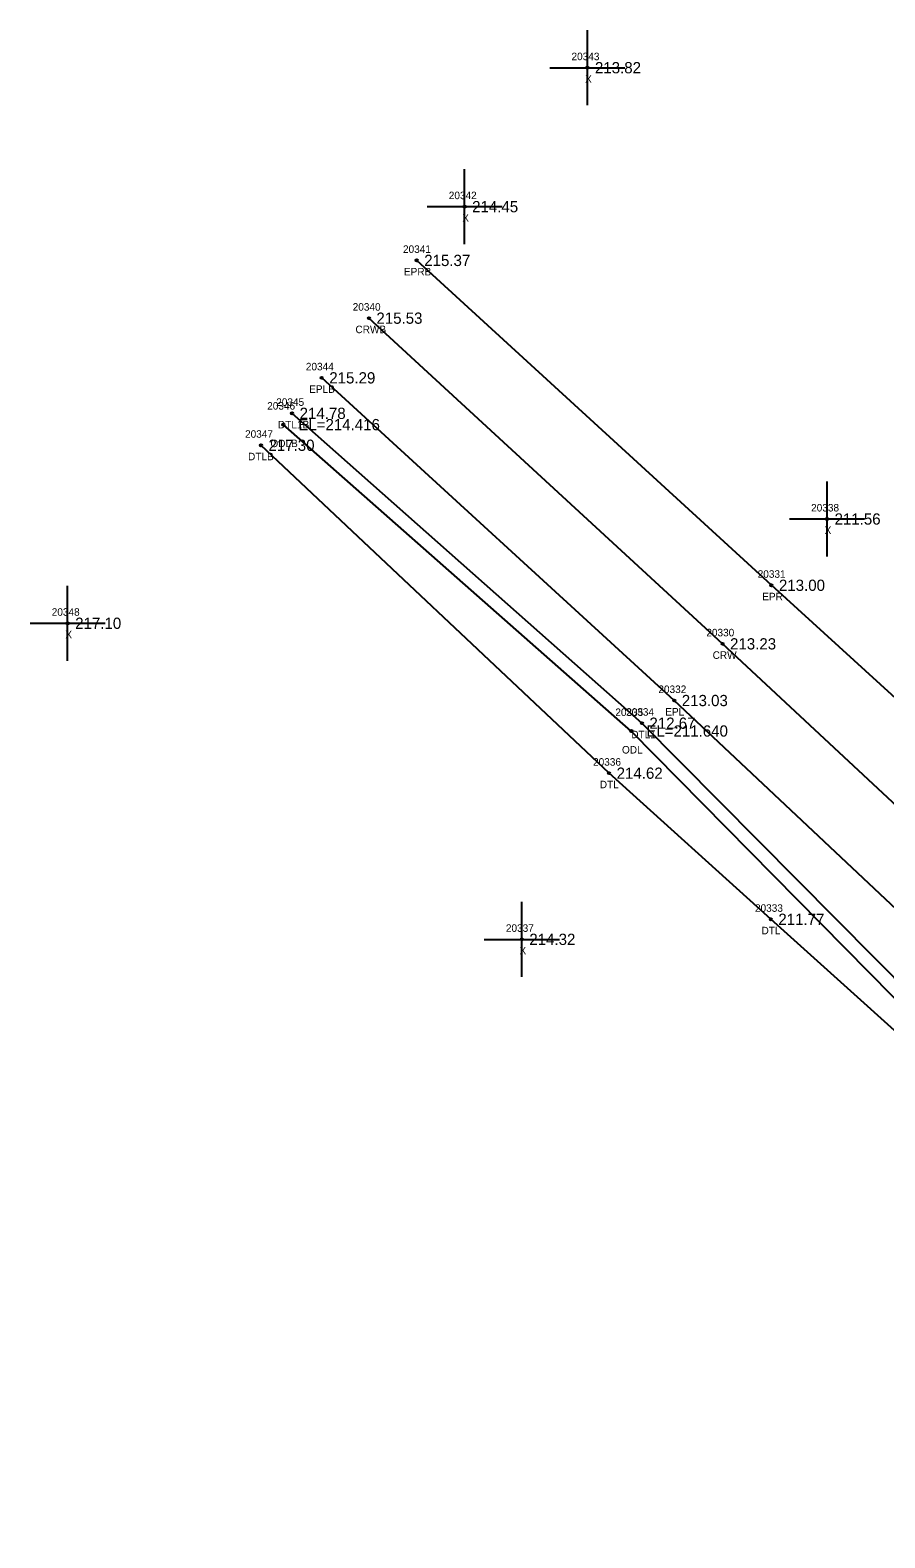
# Model space of a CAD drawing. Extents: x 2260230 to 2261304, y 1064626 to 1065587.
# Drawn here: x 2260230.3 to 2260344.2, y 1065386.5 to 1065587.3 of the extents above; entities that cross this region are included whole.
import ezdxf

# ---------------------------------------------------------------- set-up
doc = ezdxf.new("R2010")
doc.units = 0
for name, color, linetype in [('RD_DTM_BkLn1', 7, 'Continuous'), ('RD_EX_H2O', 7, 'Continuous'), ('RD_EX_H2O_txCode', 7, 'Continuous'), ('RD_EX_Misc', 7, 'Continuous'), ('RD_EX_Misc_txCode', 7, 'Continuous'), ('RD_EX_Road', 7, 'Continuous'), ('RD_EX_Road_txCode', 7, 'Continuous'), ('RD_EX_TX_H2O_ELEV', 7, 'Continuous'), ('RD_EX_TX_Misc_ELEV', 7, 'Continuous'), ('RD_EX_TX_Road_ELEV', 7, 'Continuous'), ('RD_HC_Survey_ELEV', 7, 'Continuous'), ('RD_HC_Survey_txCode', 7, 'Continuous'), ('RD_SMD_Locator', 7, 'Continuous')]:
    doc.layers.add(name, color=color, linetype=linetype)

msp = doc.modelspace()

# ---------------------------------------------------------------- linework, layer by layer
at = {"layer": 'RD_DTM_BkLn1'}
msp.add_lwpolyline([(2260460.75, 1065377.06), (2260391.17, 1065441.67), (2260322.55, 1065505.55), (2260275.44, 1065548.93)], dxfattribs=at)
at = {"layer": 'RD_EX_H2O'}
for points in [[(2260383.23, 1065420.03), (2260384.24, 1065421.93), (2260311.81, 1065494.98), (2260265.21, 1065536.25)], [(2260383.23, 1065420.03), (2260310.39, 1065493.94), (2260264.03, 1065534.75)], [(2260383.23, 1065420.03), (2260328.98, 1065468.86), (2260307.44, 1065488.32), (2260261.06, 1065532)]]:
    msp.add_lwpolyline(points, dxfattribs=at)
at = {"layer": 'RD_EX_Misc'}
for p, q in [((2260304.55, 1065577.29), (2260304.55, 1065587.29)), ((2260299.55, 1065582.29), (2260309.55, 1065582.29)), ((2260288.19, 1065558.78), (2260288.19, 1065568.78)), ((2260283.19, 1065563.78), (2260293.19, 1065563.78)), ((2260336.47, 1065517.18), (2260336.47, 1065527.18)), ((2260331.47, 1065522.18), (2260341.47, 1065522.18)), ((2260235.31, 1065503.29), (2260235.31, 1065513.29)), ((2260230.31, 1065508.29), (2260240.31, 1065508.29)), ((2260295.81, 1065461.19), (2260295.81, 1065471.19)), ((2260290.81, 1065466.19), (2260300.81, 1065466.19))]:
    msp.add_line(p, q, dxfattribs=at)
at = {"layer": 'RD_EX_Road'}
for points in [[(2260471.29, 1065388.66), (2260408.54, 1065440.4), (2260398.69, 1065449.49), (2260347.1, 1065496.93), (2260329.06, 1065513.35), (2260281.81, 1065556.62)], [(2260450.76, 1065366.34), (2260384.25, 1065433.92), (2260316.12, 1065498), (2260269.16, 1065540.98)]]:
    msp.add_lwpolyline(points, dxfattribs=at)
at = {"layer": 'RD_SMD_Locator'}
for centre in [(2260304.55, 1065582.29), (2260288.19, 1065563.78), (2260281.81, 1065556.62), (2260275.44, 1065548.93), (2260269.16, 1065540.98), (2260265.21, 1065536.25), (2260264.03, 1065534.75), (2260261.06, 1065532), (2260336.47, 1065522.18), (2260329.06, 1065513.35), (2260235.31, 1065508.29), (2260322.55, 1065505.55), (2260316.12, 1065498), (2260310.39, 1065493.94), (2260311.81, 1065494.98), (2260307.44, 1065488.32), (2260328.98, 1065468.86), (2260295.81, 1065466.19)]:
    msp.add_circle(centre, 0.15, dxfattribs=at)

# ---------------------------------------------------------------- texts
at = {"layer": 'RD_EX_H2O_txCode'}
for s, p in [('20345', (2260263.09, 1065537.25)), ('20346', (2260261.89, 1065536.75)), ('20347', (2260258.94, 1065533)), ('DTL1B', (2260263.33, 1065534.25)), ('ODLB', (2260262.32, 1065531.75)), ('DTLB', (2260259.34, 1065530)), ('20335', (2260308.27, 1065495.94)), ('20334', (2260309.7, 1065495.98)), ('DTL1', (2260310.4, 1065492.98)), ('ODL', (2260309.15, 1065490.94)), ('20336', (2260305.3, 1065489.32)), ('DTL', (2260306.2, 1065486.32)), ('20333', (2260326.87, 1065469.86)), ('DTL', (2260327.74, 1065466.86))]:
    msp.add_text(s, height=1, dxfattribs=at).set_placement(p)
at = {"layer": 'RD_EX_Misc_txCode'}
for s, p in [('20343', (2260302.43, 1065583.29)), ('X', (2260304.24, 1065580.29)), ('20342', (2260286.08, 1065564.78)), ('X', (2260287.88, 1065561.78)), ('20338', (2260334.35, 1065523.18)), ('X', (2260336.15, 1065520.18)), ('20348', (2260233.19, 1065509.29)), ('X', (2260235, 1065506.29)), ('20337', (2260293.69, 1065467.19)), ('X', (2260295.5, 1065464.19))]:
    msp.add_text(s, height=1, dxfattribs=at).set_placement(p)
at = {"layer": 'RD_EX_Road_txCode'}
for s, p in [('20341', (2260279.98, 1065557.62)), ('EPRB', (2260280.11, 1065554.62)), ('20344', (2260267.04, 1065541.98)), ('EPLB', (2260267.48, 1065538.98)), ('20331', (2260327.23, 1065514.35)), ('EPR', (2260327.84, 1065511.35)), ('20332', (2260314, 1065499)), ('EPL', (2260314.92, 1065496))]:
    msp.add_text(s, height=1, dxfattribs=at).set_placement(p)
at = {"layer": 'RD_EX_TX_H2O_ELEV'}
for s, p in [('214.78', (2260266.21, 1065535.5)), ('EL=214.416', (2260266.03, 1065534)), ('217.30', (2260262.06, 1065531.25)), ('212.67', (2260312.81, 1065494.23)), ('EL=211.640', (2260312.39, 1065493.19)), ('214.62', (2260308.44, 1065487.57)), ('211.77', (2260329.98, 1065468.11))]:
    msp.add_text(s, height=1.5, dxfattribs=at).set_placement(p)
at = {"layer": 'RD_EX_TX_Misc_ELEV'}
for s, p in [('213.82', (2260305.55, 1065581.54)), ('214.45', (2260289.19, 1065563.03)), ('211.56', (2260337.47, 1065521.43)), ('217.10', (2260236.31, 1065507.54)), ('214.32', (2260296.81, 1065465.44))]:
    msp.add_text(s, height=1.5, dxfattribs=at).set_placement(p)
at = {"layer": 'RD_EX_TX_Road_ELEV'}
for s, p in [('215.37', (2260282.81, 1065555.87)), ('215.29', (2260270.16, 1065540.23)), ('213.00', (2260330.06, 1065512.6)), ('213.03', (2260317.12, 1065497.25))]:
    msp.add_text(s, height=1.5, dxfattribs=at).set_placement(p)
at = {"layer": 'RD_HC_Survey_ELEV'}
for s, p in [('215.53', (2260276.44, 1065548.18)), ('213.23', (2260323.55, 1065504.8))]:
    msp.add_text(s, height=1.5, dxfattribs=at).set_placement(p)
at = {"layer": 'RD_HC_Survey_txCode'}
for s, p in [('20340', (2260273.28, 1065549.93)), ('CRWB', (2260273.65, 1065546.93)), ('20330', (2260320.39, 1065506.55)), ('CRW', (2260321.23, 1065503.55))]:
    msp.add_text(s, height=1, dxfattribs=at).set_placement(p)

doc.saveas('drawing.dxf')
